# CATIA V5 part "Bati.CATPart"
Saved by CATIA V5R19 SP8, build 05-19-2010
Part number: Bati
Bounding box of the stored display mesh (mm): x -600 to 772.5, y -2100 to 2250, z -1075 to 2649.904
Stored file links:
  C:\Users\rcousturie\Desktop\EU_thinkMotion\iao\IAO_MMS_Groupe1\flacan\flacan\flacan\Bati.CATPart
  C:\Users\rcousturie\Desktop\EU_thinkMotion\iao\IAO_MMS_Groupe1\flacan\flacan\flacan\Corps verin.CATPart
  C:\Documents and Settings\flacan\Bureau\Piece IAO\Assemblage.CATProduct
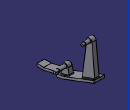
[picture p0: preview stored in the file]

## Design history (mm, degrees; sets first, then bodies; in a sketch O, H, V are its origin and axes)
External parameters (linked from other documents)
  `External.Longueur bielle` = 2100 mm
  `External.Entraxe pièce intermédiare` = 350 mm
  `External.Longueur bielle finale` = 2100 mm
Point1: (0, 1750 {= `External.Longueur bielle` -`External.Entraxe pièce intermédiare`}, 2450 {= `External.Longueur bielle` +`External.Entraxe pièce intermédiare`})
Point2: (0, 0, 0)
Body1 (main body)
  Sketch1 on yz-plane, origin (0, 0, 0), H (0, 1, 0), V (0, 0, 1)
    line L1 (2250, 300) -> (2250, 125)
    point P1 (2250, 300)
    line L2 (2250, 125) -> (0, -725)
    line L3 (0, -550) -> (2250, 300)
    point P3 (0, -725)
    point P4 (0, -550)
    reference projected point E1 (1750, 2450) from Point1
    line L4 (-1600, -900) -> (0, -550)
    point P5 (-1600, -900)
    line L5 (-2100, -1075) -> (-2100, -900)
    line L6 (-2100, -900) -> (-1600, -900)
    line L7 (-1600, -1075) -> (0, -725)
    line L8 (-1600, -1075) -> (-2100, -1075)
    point P9 (-1600, -1075)
    length L1 = 175
    distance L1 E1 = 500
    distance P4 O = 550
    distance P5 V = 1600
    distance P4 V = 0
    distance P3 V = 0
    length L5 = 175
    distance P1 H = 300
    distance L6 H = 900
    length L6 = 500
    vertical: L1 V, L5 V
    parallelism: L3 L2, L7 L4
    coincidence: P9 L7
    horizontal: L8 H
  Pad1: profile Sketch1, direction (1, 0, 0), length 150, opposite side length 600
  Sketch2 on yz-plane, origin (0, 0, 0), H (0, 1, 0), V (0, 0, 1)
    arc A1 centre (0, 0) radius 200 from (200, 0) to (-200, 0) ccw
    line L1 (-200, 0) -> (-300, -615.625)
    point P1 (-200, 0)
    point P2 (-300, -615.625)
    line L2 (200, 0) -> (300, -436.6667)
    point P3 (200, 0)
    point P4 (300, -436.6667)
    line L3 (-300, -615.625) -> (0, -550)
    point P5 (0, -550)
    line L4 (0, -550) -> (300, -436.6667)
    reference projected point E1 (0, -550) from vertex [face of Pad1 from Sketch1.L4 | end face of Pad1 | face of Pad1 from Sketch1.L3]
    reference projected line E2 (2097.6541, 242.4471) -> (0, -550) from edge [face of Pad1 from Sketch1.L3 | end face of Pad1]
    reference projected line E3 (0, -550) -> (-1600, -900) from edge [face of Pad1 from Sketch1.L4 | end face of Pad1]
    radius A1 = 200
    distance P4 V = 300
    distance P2 V = 300
    distance E1 P5 = 0
    distance P4 E2 = 0
    distance P2 E3 = 0
    coincidence: P1 H, P3 H
  Pad2: profile Sketch2, direction (1, 0, 0), length 0, opposite side length 300
  Sketch3 on yz-plane, origin (0, 0, 0), H (0, 1, 0), V (0, 0, 1)
    point P1 (1750, 2450)
    reference projected point E1 (1750, 2450) from Point1
    arc A1 centre (1750, 2450) radius 200 from (1949.1763, 2468.1328) to (1551.3811, 2473.4631) ccw
    line L1 (1949.1763, 2468.1328) -> (2150, 262.2222)
    point P4 (2150, 262.2222)
    line L2 (1551.3811, 2473.4631) -> (1250, -77.7778)
    point P5 (1250, -77.7778)
    line L3 (2150, 262.2222) -> (1250, -77.7778)
    reference projected line E2 (2250, 300) -> (0, -550) from edge [face of Pad1 from Sketch1.L3 | end face of Pad1]
    reference projected line E3 (2250, 300) -> (0, -550) from edge [face of Pad1 from Sketch1.L3 | end face of Pad1]
    distance P1 E1 = 0
    radius A1 = 200
    distance P4 E2 = 0
    distance P5 E3 = 0
    distance P5 V = 1250 {= -500mm -`External.Entraxe pièce intermédiare` +`External.Longueur bielle finale`}
    distance P4 V = 2150 {= -`External.Entraxe pièce intermédiare` +400mm+`External.Longueur bielle finale`}
    tangency: L1 A1, L2 A1
  Pad3: profile Sketch3, direction (1, 0, 0), length 0, opposite side length 300
  Sketch4 on end face of Pad2, origin (0, 0, 0), H (0, 1, 0), V (0, 0, 1)
    circle A1 centre (0, 0) radius 125
    radius A1 = 125
  Pad4: profile Sketch4, direction (1, 0, 0), length 510
  Sketch5 on end face of Pad4, origin (510, 0, 0), H (0, 1, 0), V (0, 0, 1)
    circle A1 centre (0, 0) radius 87.5
    point P1 (0, -87.5)
    radius A1 = 87.5
    coincidence: A1 P1, P1 V
  Pad5: profile Sketch5, direction (1, 0, 0), length 262.5
  Sketch6 on end face of Pad3, origin (0, 0, 0), H (0, 1, 0), V (0, 0, 1)
    circle A1 centre (1750, 2450) radius 125
    point P1 (1750, 2450)
    reference projected point E1 (1750, 2450) from Point1
    radius A1 = 125
    distance E1 P1 = 0
  Pad6: profile Sketch6, direction (1, 0, 0), length 350
  Sketch7 on end face of Pad6, origin (350, 0, 0), H (0, 1, 0), V (0, 0, 1)
    circle A1 centre (1750, 2450) radius 87.5
    point P1 (1750, 2450)
    reference projected point E1 (1750, 2450) from Point1
    radius A1 = 87.5
    distance E1 P1 = 0
  Pad7: profile Sketch7, direction (1, 0, 0), length 175
  Sketch8 on face of Pad1 from Sketch1.L6, origin (0, 0, -900), H (1, 0, 0), V (0, 1, 0)
    line L1 (150, -2100) -> (-50, -2100)
    line L2 (-50, -2100) -> (-50, -450)
    line L3 (-50, -450) -> (150, -450)
    line L4 (150, -450) -> (150, -2100)
    reference projected line E1 (-600, -2100) -> (50, -2100) from edge [face of Pad1 from Sketch1.L5 | face of Pad1 from Sketch1.L6]
    reference projected line E2 (150, -2100) -> (150, -1600) from edge [face of Pad1 from Sketch1.L8 | end face of Pad1]
    distance L1 E1 = 0
    length L2 = 1650
    distance L4 L2 = 200
    distance L4 E2 = 0
    horizontal: L1 H, L3 H
    vertical: L2 V, L4 V
  Pocket1: profile Sketch8, direction (0, 0, -1), through (limit type 6), opposite side through (limit type 6)
  Fillet1: radius 40, on edge [face of Pocket1 from Sketch8.L3 | face of Pad1 from Sketch1.L7]
  Fillet2: radius 40, on edge [face of Pad1 from Sketch1.L4 | end face of Pad2]; edge [face of Pad1 from Sketch1.L3 | end face of Pad2]; edge [face of Pad1 from Sketch1.L4 | face of Pad2 from Sketch2.L1]; edge [start face of Pad2 | face of Pad1 from Sketch1.L4]; edge [start face of Pad2 | face of Pad1 from Sketch1.L3]; edge [face of Pad2 from Sketch2.L2 | face of Pad1 from Sketch1.L3]
  Fillet3: radius 40, on edge [start face of Pad3 | face of Pad1 from Sketch1.L3]; edge [face of Pad1 from Sketch1.L3 | end face of Pad3]; edge [face of Pad1 from Sketch1.L3 | face of Pad3 from Sketch3.L2]; edge [face of Pad3 from Sketch3.L1 | face of Pad1 from Sketch1.L3]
